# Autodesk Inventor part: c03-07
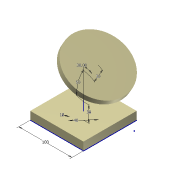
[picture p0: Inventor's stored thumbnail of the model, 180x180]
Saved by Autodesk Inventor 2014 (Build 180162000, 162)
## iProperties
Created: 2011-11
Part Number: c03-07
Material: Iron, Cast
Document SubType Name: Modeling
Designer: Thom Tremblay
Density: 7.25 g/cm^3
Mass: 1087.5 g
Surface Area: 260 cm^2
Volume: 150 cm^3
Appearance: Nylon 6
Author: Thom Tremblay
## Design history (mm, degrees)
sketch "Sketch1"
  geometry: L1 (50, -50)-(-50, -50); L2 (-50, -50)-(-50, 50); L3 (-50, 50)-(50, 50); L4 (50, 50)-(50, -50); C1 r 20 at (0, 0); C2 r 30 at (0, 0); 3 further points
  constraints: 8 end point, 2 centre point, 2 coincident, 2 midpoint, 2 parallel, 2 perpendicular, 1 horizontal, 1 horizontal alignment, 1 vertical alignment
  dimensions: "d0" = 100 distance of L2.end L3.end; "d3" = 40 diameter of C1; "d4" = 10 radial gap between concentric circles of C2 C1
extrude "Extrusion1" new body sketch "Sketch1" distance "d1" = 15; taper "d2" = 0 deg
sketch "Sketch2"
  geometry: L1 (0, 0)-(0, 30); L2 (12.794, 77.746)-(27.794, 103.727); A1 r 95.493 centre (95.493, 30) between (12.794, 77.746) and (0, 30)
  constraints: 4 end point, 2 point on circle, 2 tangent, 1 centre point, 1 vertical
  dimensions: "d5" = 30 distance of L1.start L1.end; "d7" = 50 dimension on A1; "d9" = 30 distance of L2.start L2.end; "d10" = 30 deg angle of L2 L1
sketch "Sketch3"
  geometry: L1 (12.794, 77.746)-(27.794, 103.727) reference; L2 (27.794, 103.727)-(75.425, 76.227); L3 (75.425, 76.227)-(70.425, 67.567); L4 (70.425, 67.567)-(22.794, 95.067); L5 (22.794, 95.067)-(27.794, 103.727); 2 further points
  constraints: 8 end point, 2 parallel, 2 perpendicular
  dimensions: "d11" = 110 diameter of L3 L5; "d13" = 10 distance between parallel lines of L2 L4
revolve "Revolution1" sketch "Sketch3" stored, may be unused: angle "d14" = 90 deg
body "Solid1"
